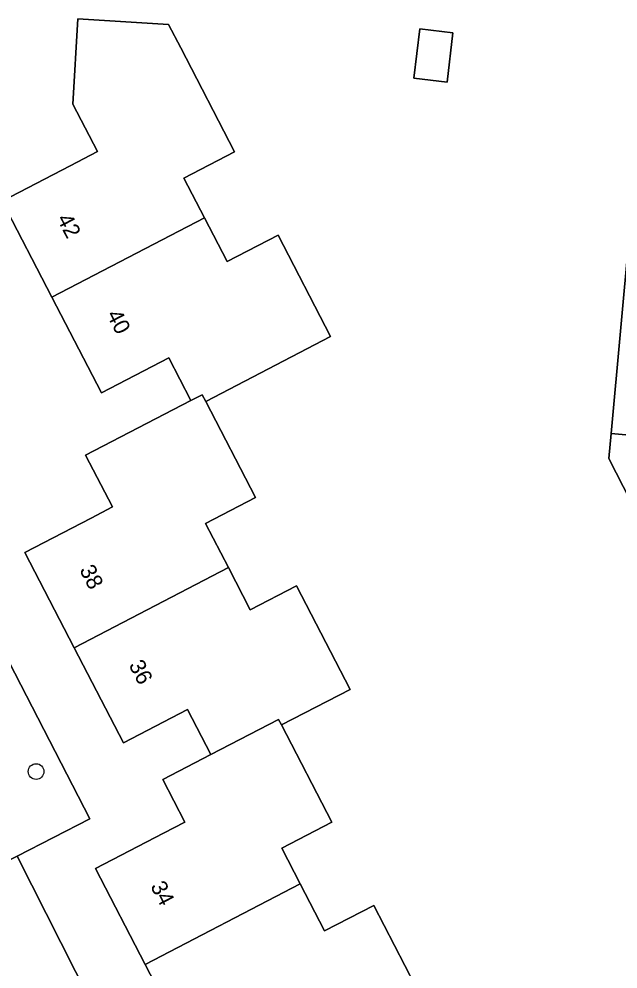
# Model space of a CAD drawing. Extents: x 162722 to 165104, y 384719 to 386284.
# Drawn here: x 163888.6 to 163926.1, y 385090.9 to 385150.3 of the extents above; entities that cross this region are included whole.
import ezdxf

# ---------------------------------------------------------------- set-up
doc = ezdxf.new("R2010")
doc.units = 0
for name, color, linetype in [('IMGEO_Boom', 7, 'Continuous'), ('IMGEO_Erf', 7, 'Continuous'), ('IMGEO_Pand', 7, 'Continuous'), ('IMGEO_Pand_nummerreeks', 7, 'Continuous'), ('IMGEO_Parkeervlak_open', 7, 'Continuous'), ('IMGEO_Voetpad_open', 7, 'Continuous')]:
    doc.layers.add(name, color=color, linetype=linetype)

msp = doc.modelspace()

# ---------------------------------------------------------------- linework, layer by layer
at = {"layer": 'IMGEO_Boom'}
msp.add_circle((163889.673, 385103.261), 0.489, dxfattribs=at)
at = {"layer": 'IMGEO_Erf'}
for points in [[(163899.61, 385085.211), (163896.499, 385091.208), (163893.388, 385097.205), (163897.642, 385099.412), (163898.981, 385100.106), (163897.602, 385102.764), (163900.6, 385104.32), (163899.141, 385107.132), (163895.13, 385105.051), (163892.046, 385110.996), (163888.962, 385116.942), (163893.113, 385119.095), (163894.445, 385119.786), (163892.77, 385123.015), (163899.356, 385126.431), (163897.969, 385129.104), (163893.753, 385126.917), (163890.648, 385132.902), (163887.541, 385138.892), (163891.8, 385141.101), (163893.513, 385141.989), (163891.973, 385144.959), (163892.29, 385150.271), (163897.958, 385149.932), (163898.722, 385148.46), (163902.091, 385141.966), (163898.921, 385140.321), (163900.198, 385137.859), (163901.623, 385135.112), (163904.803, 385136.761), (163908.087, 385130.43), (163900.283, 385126.382), (163903.401, 385120.37), (163900.274, 385118.748), (163901.698, 385116.004), (163903.067, 385113.365), (163905.956, 385114.863), (163909.311, 385108.395), (163905.022, 385106.17), (163908.166, 385100.107), (163905.031, 385098.481), (163906.196, 385096.235), (163907.719, 385093.299), (163910.786, 385094.89), (163914.022, 385088.652)], [(163934.076, 385106.062), (163925.49, 385122.819), (163925.634, 385124.386), (163926.79, 385136.924)], [(163882.314, 385121.11), (163885.455, 385114.979), (163893.028, 385100.308), (163888.495, 385097.974), (163897.601, 385079.99), (163902.096, 385082.296), (163906.672, 385073.409), (163906.693, 385073.366), (163915.816, 385055.107), (163938.946, 385066.833)]]:
    msp.add_lwpolyline(points, dxfattribs=at)
msp.add_lwpolyline([(163913.301, 385146.57), (163913.665, 385149.653), (163915.743, 385149.408), (163915.38, 385146.325)], close=True, dxfattribs=at)
at = {"layer": 'IMGEO_Pand'}
for points in [[(163902.091, 385141.966), (163898.722, 385148.46), (163897.958, 385149.932), (163892.29, 385150.271), (163891.973, 385144.959), (163893.513, 385141.989), (163891.8, 385141.101), (163887.541, 385138.892), (163890.648, 385132.902), (163900.198, 385137.859), (163898.921, 385140.321)], [(163913.301, 385146.57), (163915.38, 385146.325), (163915.743, 385149.408), (163913.665, 385149.653)], [(163900.283, 385126.382), (163908.087, 385130.43), (163904.803, 385136.761), (163901.623, 385135.112), (163900.198, 385137.859), (163890.648, 385132.902), (163893.753, 385126.917), (163897.969, 385129.104), (163899.356, 385126.431), (163900.067, 385126.799)], [(163934.161, 385123.598), (163934.624, 385128.621), (163939.488, 385128.173), (163940.181, 385135.69), (163926.79, 385136.924), (163925.634, 385124.386)], [(163903.401, 385120.37), (163900.283, 385126.382), (163900.067, 385126.799), (163899.356, 385126.431), (163892.77, 385123.015), (163894.445, 385119.786), (163893.113, 385119.095), (163888.962, 385116.942), (163892.046, 385110.996), (163901.698, 385116.004), (163900.274, 385118.748)], [(163946.07, 385112.214), (163942.568, 385119.048), (163938.196, 385116.808), (163935.921, 385121.248), (163935.481, 385121.023), (163934.161, 385123.598), (163925.634, 385124.386), (163925.49, 385122.819), (163934.076, 385106.062), (163941.667, 385109.956)], [(163905.022, 385106.17), (163909.311, 385108.395), (163905.956, 385114.863), (163903.067, 385113.365), (163901.698, 385116.004), (163892.046, 385110.996), (163895.13, 385105.051), (163899.141, 385107.132), (163900.6, 385104.32), (163904.84, 385106.521)], [(163908.166, 385100.107), (163905.022, 385106.17), (163904.84, 385106.521), (163900.6, 385104.32), (163897.602, 385102.764), (163898.981, 385100.106), (163897.642, 385099.412), (163893.388, 385097.205), (163896.499, 385091.208), (163906.196, 385096.235), (163905.031, 385098.481)], [(163896.499, 385091.208), (163899.61, 385085.211), (163903.77, 385087.369), (163905.419, 385084.19), (163909.858, 385086.492), (163914.022, 385088.652), (163910.786, 385094.89), (163907.719, 385093.299), (163906.196, 385096.235)]]:
    msp.add_lwpolyline(points, close=True, dxfattribs=at)
at = {"layer": 'IMGEO_Parkeervlak_open'}
msp.add_lwpolyline([(163888.495, 385097.974), (163880.854, 385094.169), (163894.544, 385067.072), (163904.326, 385072.183), (163906.693, 385073.366), (163906.672, 385073.409), (163902.096, 385082.296), (163897.601, 385079.99)], close=True, dxfattribs=at)
at = {"layer": 'IMGEO_Voetpad_open'}
msp.add_lwpolyline([(163882.156, 385096.449), (163881.918, 385096.889), (163877.744, 385094.776), (163878.622, 385093.046), (163880.854, 385094.169), (163888.495, 385097.974), (163893.028, 385100.308), (163885.455, 385114.979), (163883.749, 385114.101), (163886.141, 385109.315), (163886.395, 385108.759), (163886.842, 385108.987)], dxfattribs=at)

# ---------------------------------------------------------------- texts
at = {"layer": 'IMGEO_Pand_nummerreeks'}
for s, rotation, p in [('42', 297.41582, (163890.948, 385137.796)), ('40', 297.41791, (163894.057, 385131.802)), ('38', 297.41582, (163892.361, 385115.862)), ('36', 297.41629, (163895.444, 385109.917)), ('34', 297.41582, (163896.8, 385096.101))]:
    msp.add_text(s, height=1, rotation=rotation, dxfattribs=at).set_placement(p)

doc.saveas('drawing.dxf')
